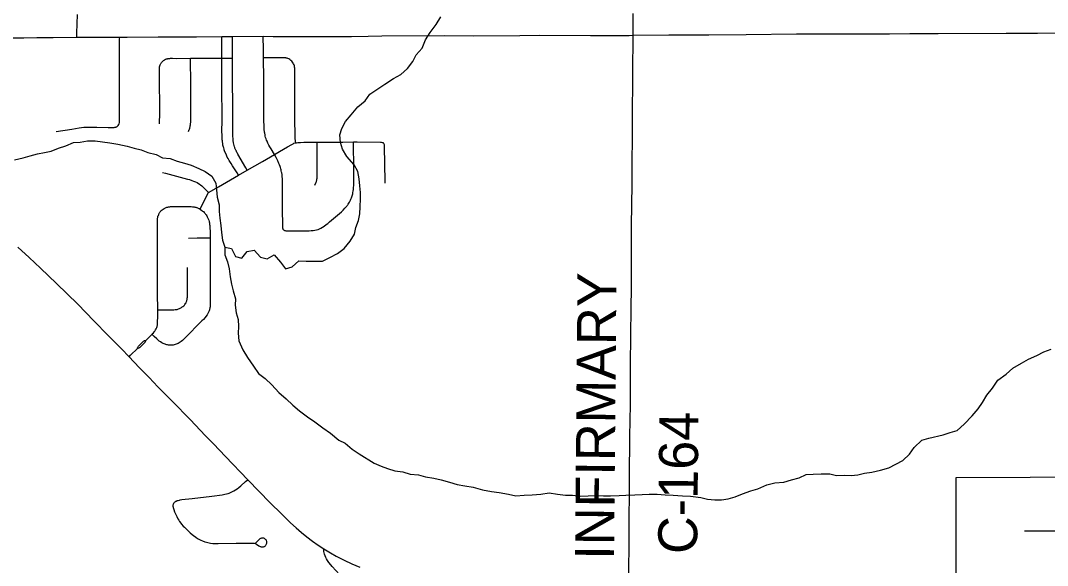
# Model space of a CAD drawing. Extents: x 0 to 34, y 0 to 22.
# Drawn here: x 14.164 to 15.659, y 11.126 to 11.919 of the extents above; entities that cross this region are included whole.
import ezdxf

# ---------------------------------------------------------------- set-up
doc = ezdxf.new("R2010")
doc.units = 0
for name, color, linetype in [('GM_X_City_Street', 7, 'Continuous'), ('GM_X_Corporation', 7, 'Continuous'), ('GM_X_County_Road', 7, 'Continuous'), ('GM_X_County_Road_Text', 7, 'Continuous'), ('GM_X_Minor_River', 7, 'Continuous'), ('GM_X_State_Route', 7, 'Continuous'), ('GM_X_Township_Road', 7, 'Continuous')]:
    doc.layers.add(name, color=color, linetype=linetype)

msp = doc.modelspace()

# ---------------------------------------------------------------- linework, layer by layer
at = {"layer": 'GM_X_City_Street'}
msp.add_lwpolyline([(15.6255, 11.1764), (15.6765, 11.1766), (15.7038, 11.1772), (15.7336, 11.1778), (15.7628, 11.1778), (15.7783, 11.1778), (15.8007, 11.1784), (15.8093, 11.1792), (15.8345, 11.1828), (15.8438, 11.1837), (15.8531, 11.1839), (15.8708, 11.1834), (15.8934, 11.183), (15.9062, 11.1827)], dxfattribs=at)
at = {"layer": 'GM_X_Corporation'}
msp.add_lwpolyline([(15.8495, 11.2548), (15.5254, 11.2537), (15.5253, 11.1122), (15.5253, 11.1082), (15.5255, 11.043), (15.543, 11.0431), (15.5511, 11.0432), (15.5441, 10.6423), (15.5944, 10.6404), (15.5805, 10.3533), (15.6058, 10.3528), (15.6026, 10.2988), (15.4241, 10.3001), (15.0377, 10.2955), (15.0355, 10.187), (15.0022, 10.1746), (14.976, 10.1565), (14.9604, 10.1322), (14.9566, 10.0947), (14.9569, 10.0643), (15.0281, 10.063), (15.0336, 9.9889), (15.0302, 9.9214), (17.2525, 9.9214)], dxfattribs=at)
at = {"layer": 'GM_X_County_Road'}
for points in [[(15.056, 11.8974), (15.0561, 11.9289)], [(15.0498, 11.1046), (15.0501, 11.1707), (15.0504, 11.2541), (15.051, 11.3138), (15.0518, 11.3602), (15.052, 11.3902), (15.0519, 11.4094), (15.0527, 11.4696), (15.053, 11.4919), (15.0534, 11.5387), (15.0535, 11.5701), (15.0537, 11.6205), (15.0539, 11.6504), (15.0543, 11.6808), (15.0545, 11.7162), (15.0547, 11.7442), (15.0548, 11.7635), (15.055, 11.7759), (15.0551, 11.7951), (15.0551, 11.8038), (15.0552, 11.8119), (15.0552, 11.8168), (15.0553, 11.8205), (15.0553, 11.823), (15.0554, 11.833), (15.0555, 11.8424), (15.056, 11.8974)], [(14.7052, 11.0345), (14.6952, 11.0447), (14.6764, 11.0637), (14.6612, 11.0792), (14.647, 11.0939), (14.6283, 11.1131), (14.6179, 11.1246), (14.6157, 11.1272), (14.6131, 11.1305), (14.6111, 11.1335), (14.6097, 11.1358), (14.6085, 11.1378), (14.6075, 11.1401), (14.6067, 11.1424), (14.6062, 11.1445), (14.6059, 11.1466), (14.6056, 11.1505)]]:
    msp.add_lwpolyline(points, dxfattribs=at)
at = {"layer": 'GM_X_Minor_River'}
for points in [[(14.4616, 11.5892), (14.4715, 11.587), (14.4769, 11.5756), (14.4864, 11.5731), (14.4942, 11.5826), (14.5041, 11.5846), (14.5136, 11.5744), (14.5231, 11.5722), (14.5336, 11.578), (14.5424, 11.5674), (14.5497, 11.5576), (14.5595, 11.5607), (14.5693, 11.5695), (14.5799, 11.5689), (14.5916, 11.5686), (14.6037, 11.569), (14.6143, 11.574), (14.6256, 11.5798), (14.6354, 11.5871), (14.644, 11.5978), (14.6504, 11.6081), (14.6522, 11.6179), (14.6563, 11.6278), (14.6581, 11.6377), (14.6584, 11.6479), (14.659, 11.6593), (14.659, 11.6688), (14.6581, 11.6783), (14.6569, 11.6885), (14.6553, 11.6991), (14.6499, 11.7089), (14.6392, 11.721), (14.6327, 11.7315), (14.63, 11.7414), (14.6291, 11.7524), (14.6321, 11.7619), (14.6373, 11.7721), (14.6456, 11.7817), (14.6553, 11.7931), (14.6658, 11.8019), (14.6726, 11.8118), (14.6944, 11.8264), (14.7072, 11.8345), (14.7178, 11.8402), (14.7275, 11.849), (14.735, 11.8593), (14.7402, 11.8688), (14.7489, 11.8788), (14.7537, 11.8906), (14.7604, 11.9016), (14.7694, 11.913), (14.7761, 11.9241)], [(14.1556, 11.7161), (14.168, 11.7192), (14.1782, 11.722), (14.1888, 11.7251), (14.199, 11.7267), (14.2088, 11.729), (14.2194, 11.7333), (14.2304, 11.7364), (14.2413, 11.7414), (14.2511, 11.7419), (14.2617, 11.7439), (14.2727, 11.7439), (14.2837, 11.7425), (14.2943, 11.7411), (14.3057, 11.7389), (14.3193, 11.7363), (14.3295, 11.7334), (14.3398, 11.7308), (14.3493, 11.7271), (14.3614, 11.7238), (14.3709, 11.7189), (14.3819, 11.7179), (14.3921, 11.7141), (14.4028, 11.7112), (14.4126, 11.7082), (14.4236, 11.7038), (14.4331, 11.6993), (14.4427, 11.6922), (14.4484, 11.6823), (14.4496, 11.6725), (14.4505, 11.6619), (14.4532, 11.6505), (14.4533, 11.6411), (14.4541, 11.6312), (14.4557, 11.6206), (14.4569, 11.6104), (14.4582, 11.5994), (14.4616, 11.5892), (14.4617, 11.5782), (14.4656, 11.5676), (14.4679, 11.5578), (14.4692, 11.546), (14.4715, 11.5354), (14.4735, 11.5256), (14.477, 11.5142), (14.4767, 11.5047), (14.4783, 11.4938), (14.481, 11.4839), (14.4815, 11.4737), (14.4812, 11.4642), (14.482, 11.4528), (14.4878, 11.4396), (14.4947, 11.4287), (14.5035, 11.4162), (14.5104, 11.4053), (14.5203, 11.3982), (14.5298, 11.3888), (14.5402, 11.3775), (14.5508, 11.3684), (14.5607, 11.3594), (14.5703, 11.3512), (14.5821, 11.3425), (14.5927, 11.335), (14.6042, 11.3264), (14.6156, 11.3185), (14.6274, 11.3084), (14.6369, 11.3039)], [(14.6369, 11.3039), (14.6468, 11.2953), (14.6571, 11.2885), (14.6791, 11.275), (14.689, 11.2706), (14.6985, 11.2672), (14.7091, 11.2639), (14.7205, 11.2621), (14.7315, 11.2591), (14.7436, 11.2577), (14.7538, 11.2551), (14.7656, 11.2529), (14.7766, 11.2507), (14.7887, 11.2471), (14.7997, 11.2441), (14.8107, 11.2419), (14.8232, 11.2401), (14.8365, 11.236), (14.8498, 11.2335), (14.8611, 11.2324), (14.8744, 11.2299), (14.885, 11.2273), (14.8971, 11.2285), (14.9088, 11.229), (14.9213, 11.2299), (14.9338, 11.2319), (14.9456, 11.2297), (14.9573, 11.2286), (14.9675, 11.2283), (14.9796, 11.2269), (14.9902, 11.2274), (15.0016, 11.2278), (15.0126, 11.2275), (15.0228, 11.2272), (15.0353, 11.2277), (15.0451, 11.2282), (15.0583, 11.229), (15.0689, 11.2295), (15.0792, 11.2299), (15.0909, 11.2297), (15.1026, 11.229), (15.114, 11.2283), (15.1276, 11.2273), (15.1394, 11.227), (15.1545, 11.2248), (15.164, 11.2226), (15.1746, 11.2216), (15.1844, 11.2216), (15.1943, 11.2232), (15.2045, 11.226), (15.215, 11.2302), (15.2271, 11.2345), (15.2373, 11.2376), (15.2505, 11.2434), (15.2622, 11.2465), (15.2754, 11.2474), (15.2864, 11.2509), (15.2974, 11.2536), (15.3079, 11.2586), (15.3181, 11.2591), (15.3295, 11.2595), (15.3423, 11.2596), (15.3518, 11.2571), (15.3632, 11.2575), (15.373, 11.2572), (15.3829, 11.2577), (15.3927, 11.2604), (15.4033, 11.2616), (15.4161, 11.2647), (15.4282, 11.2679), (15.438, 11.2736), (15.4485, 11.2786), (15.4583, 11.2878), (15.465, 11.2977), (15.4759, 11.3084), (15.4861, 11.3115), (15.5073, 11.3163), (15.5175, 11.3197), (15.5277, 11.3225), (15.5378, 11.3317), (15.5495, 11.3439), (15.5581, 11.3538), (15.5644, 11.3633), (15.5708, 11.374), (15.5787, 11.3839), (15.5869, 11.3957), (15.5989, 11.4045), (15.6087, 11.4129), (15.6211, 11.4202), (15.6313, 11.4264), (15.6434, 11.4314), (15.6536, 11.4368), (15.6641, 11.4407)]]:
    msp.add_lwpolyline(points, dxfattribs=at)
at = {"layer": 'GM_X_State_Route'}
for points in [[(14.1603, 11.5891), (14.1767, 11.5741), (14.1934, 11.5585), (14.2164, 11.5364), (14.2474, 11.506), (14.2707, 11.4822), (14.2919, 11.4604), (14.311, 11.441), (14.3221, 11.4295), (14.3291, 11.4222), (14.3378, 11.4133), (14.3513, 11.3995), (14.3642, 11.3861), (14.3849, 11.3649), (14.4114, 11.3379), (14.4332, 11.3153), (14.4451, 11.3029)], [(14.4451, 11.3029), (14.4626, 11.2846), (14.4949, 11.2509), (14.5276, 11.2173), (14.544, 11.2011), (14.5574, 11.1882), (14.5656, 11.1806), (14.5731, 11.1741), (14.5808, 11.1679), (14.5894, 11.1615), (14.5975, 11.1558), (14.6056, 11.1505), (14.6152, 11.1446), (14.6238, 11.1397), (14.6354, 11.1338), (14.6466, 11.1286), (14.6581, 11.1238)]]:
    msp.add_lwpolyline(points, dxfattribs=at)
at = {"layer": 'GM_X_Township_Road'}
for points in [[(14.2461, 11.8947), (14.2463, 11.9003), (14.2471, 11.9276)], [(14.5175, 11.8959), (14.5321, 11.8958), (14.56, 11.8958), (14.5979, 11.8958), (14.6135, 11.8957), (14.6296, 11.8956), (14.6461, 11.8958), (14.6703, 11.8962), (14.6902, 11.8964), (14.7811, 11.897), (14.8237, 11.8968), (14.8911, 11.8973), (14.9197, 11.8976), (14.9938, 11.8973), (15.0502, 11.8973), (15.056, 11.8974)], [(15.056, 11.8974), (15.108, 11.898), (15.1658, 11.8982), (15.2205, 11.8986), (15.2938, 11.8993), (15.3582, 11.8993), (15.3746, 11.8994), (15.4292, 11.8994), (15.4584, 11.8999), (15.4789, 11.9001), (15.5, 11.9002), (15.5986, 11.9007), (15.6444, 11.9005), (15.753, 11.9015), (15.7928, 11.9019), (15.8431, 11.9032), (15.8628, 11.9034), (15.876, 11.9036), (15.8984, 11.9035)], [(14.0562, 11.8937), (14.0869, 11.8937), (14.1533, 11.8938), (14.1688, 11.8939), (14.1881, 11.894), (14.2116, 11.8944), (14.2461, 11.8947)], [(14.2461, 11.8947), (14.2656, 11.8948), (14.2948, 11.8948), (14.3086, 11.8946)], [(14.3053, 11.7651), (14.306, 11.7657), (14.3065, 11.7663), (14.3073, 11.7677), (14.3077, 11.7688), (14.3081, 11.7704), (14.3082, 11.7715), (14.3083, 11.7728), (14.3083, 11.7761), (14.3084, 11.7848), (14.3083, 11.8201), (14.3082, 11.8434), (14.3084, 11.8727), (14.3084, 11.8776), (14.3085, 11.8918), (14.3086, 11.8946)], [(14.3086, 11.8946), (14.3193, 11.8947), (14.3646, 11.8949), (14.4203, 11.8953), (14.4571, 11.8955)], [(14.4571, 11.8955), (14.4726, 11.8956), (14.5175, 11.8959)], [(14.4816, 11.6938), (14.4793, 11.6973), (14.4726, 11.7077), (14.4707, 11.7107), (14.4698, 11.7122), (14.4681, 11.7151), (14.4665, 11.7179), (14.4652, 11.7203), (14.4633, 11.7243), (14.4618, 11.7278), (14.4608, 11.7307), (14.4604, 11.7319), (14.4599, 11.7338), (14.4596, 11.7347), (14.4589, 11.7377), (14.4585, 11.7399), (14.4582, 11.7423), (14.458, 11.7439), (14.4579, 11.7451), (14.4577, 11.7476), (14.4576, 11.7499), (14.4575, 11.7526), (14.4574, 11.7569), (14.4575, 11.7737), (14.4574, 11.8251), (14.4572, 11.8642), (14.4571, 11.8914), (14.4571, 11.8955)], [(14.4941, 11.701), (14.4921, 11.7045), (14.4806, 11.7244), (14.4798, 11.7259), (14.4791, 11.7271), (14.4784, 11.7285), (14.4779, 11.7296), (14.4776, 11.7302), (14.4771, 11.7313), (14.4766, 11.7324), (14.4763, 11.7332), (14.4759, 11.7343), (14.4756, 11.7352), (14.475, 11.7372), (14.4743, 11.7409), (14.4738, 11.7441), (14.4735, 11.7468), (14.4733, 11.7506), (14.473, 11.7628), (14.4727, 11.8642), (14.4726, 11.8927), (14.4726, 11.8956)], [(14.5471, 11.6143), (14.5467, 11.615), (14.5464, 11.6157), (14.5462, 11.6164), (14.5461, 11.6173), (14.546, 11.6179), (14.546, 11.6187), (14.5455, 11.6466), (14.5454, 11.6621), (14.5453, 11.674), (14.5453, 11.6818), (14.5453, 11.6861), (14.5453, 11.6887), (14.5451, 11.6919), (14.5448, 11.6949), (14.5445, 11.6973), (14.5443, 11.6983), (14.5438, 11.7002), (14.5435, 11.7015), (14.543, 11.7033), (14.5425, 11.7051), (14.542, 11.7066), (14.5411, 11.7088), (14.5401, 11.7111), (14.5385, 11.7146), (14.5361, 11.7195), (14.5337, 11.7239), (14.5288, 11.7323), (14.5271, 11.7352), (14.5258, 11.7375), (14.5244, 11.7403), (14.5236, 11.742), (14.523, 11.7435), (14.5224, 11.7448), (14.5218, 11.7467), (14.521, 11.7489), (14.5205, 11.7506), (14.5201, 11.7527), (14.5196, 11.7551), (14.5194, 11.7563), (14.5191, 11.7579), (14.519, 11.7591), (14.5188, 11.762), (14.5186, 11.7677), (14.5185, 11.7711), (14.5185, 11.7876), (14.5184, 11.8068), (14.5183, 11.8123), (14.5182, 11.8277), (14.5182, 11.8339), (14.5179, 11.8647), (14.5178, 11.8804), (14.5176, 11.8915), (14.5175, 11.8959)], [(14.3666, 11.7684), (14.3666, 11.7703), (14.3669, 11.7827), (14.3671, 11.7933), (14.3668, 11.8058), (14.3667, 11.8175), (14.3663, 11.843), (14.3663, 11.8442), (14.3664, 11.8465), (14.3664, 11.8478), (14.3665, 11.8494), (14.3667, 11.8513), (14.367, 11.8528), (14.3676, 11.8545), (14.3683, 11.8561), (14.3688, 11.8569), (14.3695, 11.8579), (14.3702, 11.8588), (14.3713, 11.8599), (14.3725, 11.8608), (14.3732, 11.8613), (14.3739, 11.8617), (14.3751, 11.8624), (14.3757, 11.8626), (14.3766, 11.8629), (14.3773, 11.8631), (14.378, 11.8633), (14.3788, 11.8635), (14.3795, 11.8636), (14.3813, 11.8638), (14.3826, 11.8639), (14.3841, 11.8639), (14.3855, 11.8639), (14.3919, 11.8638), (14.4118, 11.864), (14.4226, 11.8641), (14.448, 11.8642), (14.4572, 11.8642), (14.4604, 11.8642), (14.4727, 11.8642)], [(14.4088, 11.7573), (14.4093, 11.7587), (14.4098, 11.7601), (14.4101, 11.761), (14.4105, 11.7624), (14.4108, 11.7633), (14.4109, 11.7642), (14.4112, 11.7655), (14.4115, 11.7669), (14.4116, 11.7679), (14.4118, 11.7695), (14.4119, 11.7703), (14.412, 11.7714), (14.4122, 11.775), (14.4123, 11.7785), (14.412, 11.8129), (14.4119, 11.828), (14.4118, 11.8611), (14.4118, 11.864)], [(14.5648, 11.7409), (14.5646, 11.7424), (14.5643, 11.7443), (14.5641, 11.7466), (14.5637, 11.7803), (14.5636, 11.8082), (14.5635, 11.8243), (14.5635, 11.8407), (14.5634, 11.8475), (14.5633, 11.8497), (14.5632, 11.851), (14.5628, 11.8528), (14.5624, 11.8542), (14.5617, 11.856), (14.5611, 11.857), (14.56, 11.8585), (14.5591, 11.8596), (14.5577, 11.8609), (14.5569, 11.8615), (14.5562, 11.862), (14.5547, 11.8629), (14.5534, 11.8635), (14.5525, 11.8639), (14.551, 11.8642), (14.5502, 11.8644), (14.5493, 11.8645), (14.5486, 11.8645), (14.5473, 11.8646), (14.5243, 11.8647), (14.5179, 11.8647)], [(14.2162, 11.7573), (14.2389, 11.761), (14.2494, 11.7628), (14.2532, 11.7633), (14.2566, 11.7636), (14.2608, 11.7637), (14.2661, 11.7637), (14.2751, 11.7635)], [(14.2751, 11.7635), (14.292, 11.7633), (14.2994, 11.7633), (14.3003, 11.7634), (14.3015, 11.7635), (14.3028, 11.7638), (14.3036, 11.7641), (14.3043, 11.7644), (14.3053, 11.7651)], [(14.4256, 11.6445), (14.4344, 11.6624), (14.438, 11.6689), (14.4523, 11.6769), (14.4816, 11.6938), (14.4941, 11.701), (14.5165, 11.7139), (14.5337, 11.7239), (14.5412, 11.7282), (14.553, 11.7352), (14.5589, 11.7387), (14.5609, 11.7397), (14.5622, 11.7402), (14.5642, 11.7408), (14.5648, 11.7409), (14.5659, 11.7411), (14.568, 11.7414), (14.5688, 11.7414), (14.5716, 11.7416), (14.5766, 11.7417), (14.5961, 11.7418), (14.5984, 11.7419), (14.6158, 11.742), (14.6332, 11.742), (14.6488, 11.7422), (14.6543, 11.7422), (14.688, 11.742), (14.6893, 11.7418), (14.6904, 11.7416), (14.6914, 11.7412), (14.6923, 11.7407)], [(14.5471, 11.6143), (14.5477, 11.6137), (14.5483, 11.6134), (14.5493, 11.6132), (14.5502, 11.6131), (14.5509, 11.6131), (14.5518, 11.613), (14.5541, 11.613), (14.5668, 11.613), (14.5842, 11.613), (14.5871, 11.6132), (14.5903, 11.6134), (14.5928, 11.6138), (14.5952, 11.6143), (14.5973, 11.6149), (14.5992, 11.6156), (14.6013, 11.6166), (14.6036, 11.618), (14.6061, 11.6196), (14.6092, 11.6219), (14.6115, 11.6238), (14.6141, 11.626), (14.6312, 11.6407), (14.6338, 11.6432), (14.6363, 11.6458), (14.6376, 11.6472), (14.639, 11.6489), (14.6397, 11.6499), (14.6404, 11.6508), (14.6411, 11.6519), (14.642, 11.6531), (14.6428, 11.6544), (14.6434, 11.6555), (14.6443, 11.6573), (14.6451, 11.659), (14.6458, 11.6607), (14.6464, 11.6624), (14.6473, 11.6654), (14.6477, 11.6669), (14.6481, 11.6687), (14.6484, 11.6706), (14.6487, 11.6729), (14.6489, 11.6758), (14.6491, 11.6787), (14.6493, 11.6824), (14.6494, 11.6857), (14.6491, 11.7054), (14.6488, 11.7384), (14.6488, 11.7422)], [(14.5928, 11.6795), (14.5944, 11.6836), (14.5948, 11.6849), (14.5951, 11.6857), (14.5954, 11.6868), (14.5955, 11.6876), (14.5957, 11.6883), (14.5958, 11.6893), (14.5959, 11.6906), (14.596, 11.6918), (14.596, 11.6934), (14.596, 11.6941), (14.596, 11.6957), (14.596, 11.721), (14.5961, 11.7392), (14.5961, 11.7418)], [(14.6948, 11.6823), (14.6948, 11.6848), (14.6941, 11.7356), (14.694, 11.7372), (14.6939, 11.7382), (14.6936, 11.7391), (14.6932, 11.7398), (14.6923, 11.7407)], [(14.3709, 11.6977), (14.3754, 11.6966), (14.4071, 11.6882), (14.4101, 11.6874), (14.4137, 11.6862), (14.4161, 11.6854), (14.419, 11.6841), (14.4211, 11.6831), (14.4247, 11.681), (14.4263, 11.68), (14.4282, 11.6786), (14.4298, 11.6771), (14.438, 11.6689)], [(14.3639, 11.498), (14.3637, 11.5219), (14.3635, 11.5555), (14.3634, 11.6096), (14.3634, 11.6244), (14.3635, 11.6272), (14.3636, 11.6286), (14.3636, 11.6298), (14.3638, 11.6311), (14.364, 11.6324), (14.3643, 11.634), (14.3648, 11.6354), (14.3653, 11.6367), (14.3661, 11.6384), (14.3665, 11.6391), (14.3671, 11.6399), (14.3675, 11.6405), (14.3681, 11.6412), (14.3686, 11.6419), (14.3695, 11.6427), (14.3704, 11.6435), (14.3717, 11.6445), (14.3731, 11.6453), (14.3754, 11.6464), (14.3772, 11.6471), (14.3784, 11.6475), (14.3797, 11.6477), (14.3813, 11.648), (14.3826, 11.6481), (14.3845, 11.6481), (14.3857, 11.6481), (14.3887, 11.6482), (14.396, 11.6483), (14.4044, 11.6483), (14.4095, 11.6482), (14.4124, 11.6482), (14.4146, 11.648), (14.4157, 11.6479), (14.4169, 11.6477), (14.4179, 11.6475), (14.4187, 11.6474), (14.4195, 11.6471), (14.4204, 11.6469), (14.421, 11.6467), (14.4216, 11.6465), (14.423, 11.6459), (14.4241, 11.6454), (14.4256, 11.6445)], [(14.4256, 11.6445), (14.4264, 11.644), (14.428, 11.6427), (14.4292, 11.6417), (14.4303, 11.6408), (14.4314, 11.6397), (14.432, 11.6389), (14.4329, 11.6379), (14.4334, 11.6373), (14.4343, 11.6361), (14.4352, 11.6347), (14.4361, 11.6332), (14.4365, 11.6323), (14.437, 11.6312), (14.4374, 11.6302), (14.4378, 11.6293), (14.4381, 11.6283), (14.4386, 11.6267), (14.4388, 11.6259), (14.4391, 11.6243), (14.4393, 11.6228), (14.4394, 11.6221), (14.4396, 11.6208), (14.4397, 11.6195), (14.4399, 11.6163), (14.44, 11.6129), (14.4401, 11.6096), (14.4403, 11.6027)], [(14.4403, 11.6027), (14.4403, 11.5925), (14.4403, 11.5478), (14.4404, 11.5273), (14.4404, 11.5181), (14.4403, 11.5107), (14.4402, 11.5069), (14.4402, 11.5051), (14.4401, 11.504), (14.44, 11.5025), (14.4397, 11.5007), (14.4396, 11.4998), (14.4393, 11.4988), (14.4391, 11.4979), (14.4387, 11.4967), (14.4379, 11.4947), (14.4374, 11.4936), (14.4357, 11.4908), (14.4341, 11.4885), (14.4328, 11.4868), (14.4304, 11.4841), (14.4282, 11.4818), (14.4034, 11.4569), (14.3998, 11.4536), (14.398, 11.4521), (14.3966, 11.4511), (14.395, 11.4499), (14.3938, 11.4492), (14.3922, 11.4484), (14.3907, 11.4478), (14.3893, 11.4474), (14.3864, 11.4467), (14.384, 11.4465), (14.3821, 11.4465), (14.381, 11.4466), (14.3795, 11.4468), (14.3782, 11.447), (14.3774, 11.4471), (14.3758, 11.4475), (14.3747, 11.4478), (14.3732, 11.4483), (14.3717, 11.449), (14.37, 11.4499), (14.3679, 11.4513), (14.3662, 11.4525), (14.3625, 11.4557), (14.3587, 11.4593), (14.356, 11.4619)], [(14.4086, 11.6024), (14.4212, 11.6026), (14.4361, 11.6027), (14.4403, 11.6027)], [(14.3639, 11.498), (14.3686, 11.498), (14.3875, 11.4982), (14.3891, 11.4983), (14.3902, 11.4984), (14.3914, 11.4985), (14.3921, 11.4987), (14.3932, 11.4989), (14.3943, 11.4993), (14.3958, 11.4999), (14.3983, 11.5013), (14.3996, 11.5021), (14.4005, 11.5028), (14.4019, 11.5039), (14.4028, 11.5049), (14.4036, 11.5058), (14.4044, 11.507), (14.4051, 11.5084), (14.4055, 11.5092), (14.4059, 11.5102), (14.4063, 11.5113), (14.4065, 11.512), (14.4067, 11.5131), (14.4069, 11.514), (14.407, 11.5149), (14.4071, 11.5162), (14.4072, 11.5174), (14.4073, 11.5189), (14.4073, 11.52), (14.4073, 11.5217), (14.4073, 11.5247), (14.4071, 11.5361), (14.4071, 11.5596)], [(14.3555, 11.4623), (14.356, 11.4629), (14.3576, 11.4645), (14.3586, 11.4658), (14.3596, 11.4671), (14.3608, 11.4688), (14.3615, 11.4701), (14.3624, 11.4722), (14.3629, 11.4738), (14.3634, 11.476), (14.3637, 11.4774), (14.3638, 11.48), (14.3639, 11.4883), (14.3639, 11.498)], [(14.3346, 11.4419), (14.3355, 11.4421), (14.3368, 11.4426), (14.3376, 11.4431), (14.3385, 11.4438), (14.3429, 11.4481), (14.3447, 11.45), (14.3452, 11.4505), (14.3457, 11.4511), (14.3462, 11.452), (14.3464, 11.4529), (14.3464, 11.4536), (14.3515, 11.4584), (14.3555, 11.4623)], [(14.3346, 11.4419), (14.3347, 11.4426), (14.3348, 11.4432), (14.3353, 11.4442), (14.3359, 11.445), (14.3434, 11.4524), (14.344, 11.4528), (14.3445, 11.4532), (14.3453, 11.4535), (14.3464, 11.4536)], [(14.3221, 11.4295), (14.3245, 11.4319), (14.3346, 11.4419)], [(14.3869, 11.2161), (14.3877, 11.2172), (14.3885, 11.218), (14.3892, 11.2187), (14.3902, 11.2194), (14.391, 11.2198), (14.3915, 11.2201), (14.3923, 11.2204), (14.3935, 11.2208), (14.3954, 11.2213), (14.3964, 11.2215), (14.3992, 11.2219), (14.4138, 11.2236), (14.4428, 11.2268), (14.4578, 11.2288), (14.4618, 11.2296), (14.464, 11.2301), (14.4663, 11.2309), (14.4677, 11.2314), (14.4698, 11.2323), (14.4719, 11.2332), (14.4746, 11.2347), (14.4773, 11.2363), (14.4795, 11.2378), (14.4819, 11.2396), (14.4847, 11.2419), (14.4915, 11.248), (14.4949, 11.2509)], [(14.3869, 11.2161), (14.3866, 11.2155), (14.3863, 11.2147), (14.3861, 11.2136), (14.386, 11.2124), (14.3862, 11.2111), (14.3864, 11.2102), (14.3868, 11.2088), (14.3873, 11.2073), (14.3885, 11.2041), (14.3901, 11.2003), (14.3915, 11.1973), (14.3933, 11.1939), (14.3944, 11.1922), (14.3957, 11.1902), (14.3975, 11.1877), (14.3986, 11.1864), (14.401, 11.1835), (14.4028, 11.1816), (14.4085, 11.176), (14.4111, 11.1735), (14.4139, 11.1711), (14.4159, 11.1696), (14.4194, 11.1671), (14.4219, 11.1655), (14.4239, 11.1643), (14.4265, 11.163), (14.429, 11.1619), (14.4327, 11.1605), (14.4347, 11.1599), (14.4388, 11.159), (14.4407, 11.1586), (14.4443, 11.1582), (14.4472, 11.158), (14.452, 11.1579), (14.4782, 11.1584), (14.5019, 11.1587), (14.5032, 11.1586), (14.5045, 11.1585), (14.5056, 11.1582), (14.5066, 11.1578), (14.5077, 11.1572), (14.5112, 11.1548), (14.5121, 11.1542), (14.5128, 11.1538), (14.5134, 11.1536), (14.5143, 11.1533), (14.5153, 11.1531), (14.5159, 11.153), (14.5171, 11.1531), (14.5177, 11.1532), (14.5189, 11.1536), (14.5195, 11.1539), (14.5202, 11.1544), (14.5208, 11.155), (14.5212, 11.1555), (14.5219, 11.1566), (14.5222, 11.1574), (14.5225, 11.1584), (14.5227, 11.1593), (14.5227, 11.1601), (14.5226, 11.1609), (14.5224, 11.1617), (14.5222, 11.1623), (14.5216, 11.1632), (14.5209, 11.164), (14.5204, 11.1645), (14.5197, 11.165), (14.5191, 11.1654), (14.5184, 11.1656), (14.5174, 11.1659), (14.5167, 11.166), (14.5157, 11.166), (14.5148, 11.1658), (14.514, 11.1655), (14.5133, 11.1652), (14.5127, 11.1648), (14.512, 11.1643), (14.5115, 11.1639), (14.5104, 11.1629), (14.509, 11.1615), (14.5081, 11.1605), (14.507, 11.1595), (14.5061, 11.1587)]]:
    msp.add_lwpolyline(points, dxfattribs=at)

# ---------------------------------------------------------------- texts
at = {"layer": 'GM_X_County_Road_Text'}
for s, rotation, p in [('INFIRMARY', 89.5139, (15.0281, 11.1342)), ('C-164', 89.4572, (15.149, 11.1426))]:
    msp.add_text(s, height=0.05682, rotation=rotation, dxfattribs=at).set_placement(p)

doc.saveas('drawing.dxf')
